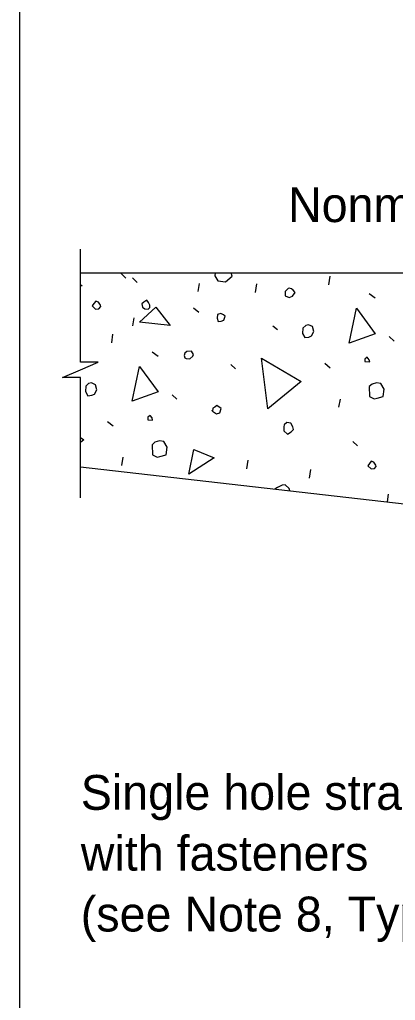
# Model space of a CAD drawing. Extents: x 112544 to 112597.1, y 111084 to 111107.1.
# Drawn here: x 112543.992 to 112545.622, y 111091.281 to 111095.538 of the extents above; entities that cross this region are included whole.
import ezdxf

# ---------------------------------------------------------------- set-up
doc = ezdxf.new("R2010")
doc.units = 0
for name, color, linetype in [('ActivePts-ConstElements', 7, 'Continuous'), ('Dimension', 7, 'Continuous'), ('Miscellaneous', 7, 'Continuous'), ('SupstrConc', 7, 'Continuous'), ('TextStructures', 7, 'Continuous')]:
    doc.layers.add(name, color=color, linetype=linetype)

msp = doc.modelspace()

# ---------------------------------------------------------------- linework, layer by layer
at = {"layer": 'ActivePts-ConstElements'}
msp.add_lwpolyline([(112543.9918, 111085.9039), (112574.7797, 111085.9039), (112574.7797, 111105.3634), (112543.9918, 111105.3634)], close=True, dxfattribs=at)
at = {"layer": 'Dimension'}
msp.add_lwpolyline([(112544.2555, 111093.4617), (112544.2555, 111093.984), (112544.178, 111093.984), (112544.2555, 111094.0177), (112544.333, 111094.0515), (112544.2555, 111094.0515), (112544.2555, 111094.5418)], dxfattribs=at)
at = {"layer": 'Miscellaneous'}
for p, q in [((112544.432, 111094.4358), (112544.4529, 111094.4156)), ((112544.4808, 111094.4179), (112544.5018, 111094.3976)), ((112545.3327, 111094.3873), (112545.3382, 111094.425)), ((112544.2555, 111094.3888), (112544.2625, 111094.3826)), ((112544.7662, 111094.3572), (112544.7723, 111094.3924)), ((112545.0155, 111094.3541), (112545.021, 111094.3918)), ((112545.5086, 111094.349), (112545.5344, 111094.3301)), ((112544.7462, 111094.2871), (112544.7696, 111094.2675)), ((112544.4825, 111094.2087), (112544.4886, 111094.2439)), ((112545.0907, 111094.2086), (112545.1104, 111094.1932)), ((112544.391, 111094.135), (112544.3964, 111094.1727)), ((112545.5949, 111094.1625), (112545.6158, 111094.1422)), ((112544.5669, 111094.0967), (112544.5926, 111094.0777)), ((112544.908, 111094.0406), (112544.9283, 111094.0227)), ((112545.3154, 111094.0462), (112545.3388, 111094.0266)), ((112544.6531, 111093.9101), (112544.674, 111093.8899)), ((112545.3768, 111093.8556), (112545.3829, 111093.8909)), ((112544.3736, 111093.7939), (112544.397, 111093.7742)), ((112545.4376, 111093.7062), (112545.4579, 111093.6884)), ((112544.4351, 111093.6033), (112544.4411, 111093.6385)), ((112544.9775, 111093.5881), (112544.9829, 111093.6258)), ((112545.2498, 111093.5472), (112545.2553, 111093.5849)), ((112545.587, 111093.4451), (112545.5918, 111093.4784))]:
    msp.add_line(p, q, dxfattribs=at)
for points in [[(112544.8385, 111094.4257), (112544.8522, 111094.4035), (112544.8844, 111094.3992), (112544.9137, 111094.4251), (112544.9099, 111094.4392)], [(112544.8404, 111094.4392), (112544.8385, 111094.4257)], [(112545.144, 111094.3575), (112545.1437, 111094.3393), (112545.1615, 111094.3311), (112545.1753, 111094.3374), (112545.1865, 111094.3533), (112545.1785, 111094.3641), (112545.1717, 111094.37), (112545.1608, 111094.3723), (112545.1559, 111094.371), (112545.144, 111094.3575)], [(112544.3064, 111094.2961), (112544.3206, 111094.2817), (112544.3357, 111094.2832), (112544.3434, 111094.293), (112544.3421, 111094.2979), (112544.3334, 111094.3111), (112544.3218, 111094.3157), (112544.3141, 111094.3059), (112544.3064, 111094.2961)], [(112544.5254, 111094.29), (112544.5352, 111094.2823), (112544.5486, 111094.2807), (112544.557, 111094.2882), (112544.5568, 111094.2985), (112544.5511, 111094.3099), (112544.5431, 111094.3207), (112544.5299, 111094.312), (112544.5215, 111094.3045), (112544.5254, 111094.29)], [(112544.5119, 111094.2243), (112544.5824, 111094.2898), (112544.645, 111094.2108), (112544.5119, 111094.2243)], [(112545.4213, 111094.1341), (112545.4533, 111094.285), (112545.5346, 111094.1748), (112545.4213, 111094.1341)], [(112544.8488, 111094.2421), (112544.8527, 111094.2276), (112544.8654, 111094.2285), (112544.8769, 111094.2341), (112544.8826, 111094.2512), (112544.8759, 111094.2571), (112544.8643, 111094.2618), (112544.8498, 111094.2579), (112544.8488, 111094.2421)], [(112545.2201, 111094.1992), (112545.2186, 111094.1756), (112545.2287, 111094.1575), (112545.2462, 111094.1597), (112545.2576, 111094.1653), (112545.2682, 111094.1837), (112545.2624, 111094.2054), (112545.2447, 111094.2136), (112545.2326, 111094.2104), (112545.2201, 111094.1992)], [(112544.7086, 111094.07), (112544.7147, 111094.0664), (112544.7305, 111094.0655), (112544.7431, 111094.0766), (112544.7459, 111094.0851), (112544.7372, 111094.0983), (112544.7166, 111094.098), (112544.7083, 111094.0906), (112544.706, 111094.0796), (112544.7086, 111094.07)], [(112545.0683, 111093.848), (112545.0403, 111094.0683), (112545.2125, 111093.9669), (112545.0683, 111093.848)], [(112545.4893, 111094.054), (112545.5106, 111094.0519), (112545.508, 111094.0616), (112545.4999, 111094.0724), (112545.4892, 111094.0643), (112545.4893, 111094.054)], [(112544.4795, 111093.8818), (112544.5115, 111094.0327), (112544.5928, 111093.9225), (112544.4795, 111093.8818)], [(112544.2783, 111093.9469), (112544.2769, 111093.9232), (112544.2869, 111093.9052), (112544.3044, 111093.9073), (112544.3159, 111093.913), (112544.3265, 111093.9313), (112544.3206, 111093.9531), (112544.3029, 111093.9613), (112544.2908, 111093.958), (112544.2783, 111093.9469)], [(112545.5081, 111093.9451), (112545.5095, 111093.9015), (112545.5303, 111093.8915), (112545.5423, 111093.8948), (112545.5689, 111093.9019), (112545.5732, 111093.9341), (112545.5589, 111093.9587), (112545.54, 111093.9615), (112545.5207, 111093.9563), (112545.5081, 111093.9451)], [(112544.8277, 111093.8379), (112544.8461, 111093.8273), (112544.8606, 111093.8312), (112544.8657, 111093.8507), (112544.8467, 111093.8637), (112544.8383, 111093.8563), (112544.8293, 111093.8513), (112544.8277, 111093.8379), (112544.8264, 111093.8427)], [(112544.5476, 111093.8016), (112544.5688, 111093.7996), (112544.5662, 111093.8092), (112544.5582, 111093.82), (112544.5474, 111093.8119), (112544.5476, 111093.8016)], [(112545.1381, 111093.7709), (112545.1378, 111093.7527), (112545.1544, 111093.7391), (112545.17, 111093.7484), (112545.1802, 111093.7589), (112545.1769, 111093.771), (112545.1676, 111093.7866), (112545.1511, 111093.79), (112545.1386, 111093.7788), (112545.1381, 111093.7709)], [(112544.2555, 111093.7235), (112544.2707, 111093.7145), (112544.2555, 111093.702)], [(112544.5664, 111093.6928), (112544.5677, 111093.6492), (112544.5885, 111093.6392), (112544.6006, 111093.6424), (112544.6271, 111093.6496), (112544.6314, 111093.6818), (112544.6171, 111093.7064), (112544.5982, 111093.7091), (112544.5789, 111093.7039), (112544.5664, 111093.6928)], [(112544.725, 111093.5645), (112544.748, 111093.6716), (112544.8354, 111093.6355), (112544.725, 111093.5645)], [(112545.5018, 111093.6018), (112545.516, 111093.5875), (112545.5311, 111093.589), (112545.5388, 111093.5988), (112545.5375, 111093.6036), (112545.5288, 111093.6168), (112545.5172, 111093.6215), (112545.5095, 111093.6116), (112545.5018, 111093.6018)], [(112545.1634, 111093.4932), (112545.1608, 111093.5027), (112545.1436, 111093.5188), (112545.1309, 111093.5179), (112545.1104, 111093.5073), (112545.0991, 111093.5005)]]:
    msp.add_lwpolyline(points, dxfattribs=at)
at = {"layer": 'SupstrConc'}
for p, q in [((112544.2555, 111094.4392), (112552.7436, 111094.4392)), ((112544.2555, 111093.5963), (112545.7099, 111093.4312))]:
    msp.add_line(p, q, dxfattribs=at)

# ---------------------------------------------------------------- texts
at = {"layer": 'Dimension'}
for s, p in [('Single hole straps', (112544.257, 111092.1083)), ('with fasteners', (112544.257, 111091.8443)), ('(see Note 8, Typ.)', (112544.257, 111091.5803))]:
    msp.add_text(s, height=0.1512, dxfattribs=at).set_placement(p)
at = {"layer": 'TextStructures'}
msp.add_text('Nonmetallic Junction Box', height=0.1512, dxfattribs=at).set_placement((112545.1559, 111094.6591))

doc.saveas('drawing.dxf')
